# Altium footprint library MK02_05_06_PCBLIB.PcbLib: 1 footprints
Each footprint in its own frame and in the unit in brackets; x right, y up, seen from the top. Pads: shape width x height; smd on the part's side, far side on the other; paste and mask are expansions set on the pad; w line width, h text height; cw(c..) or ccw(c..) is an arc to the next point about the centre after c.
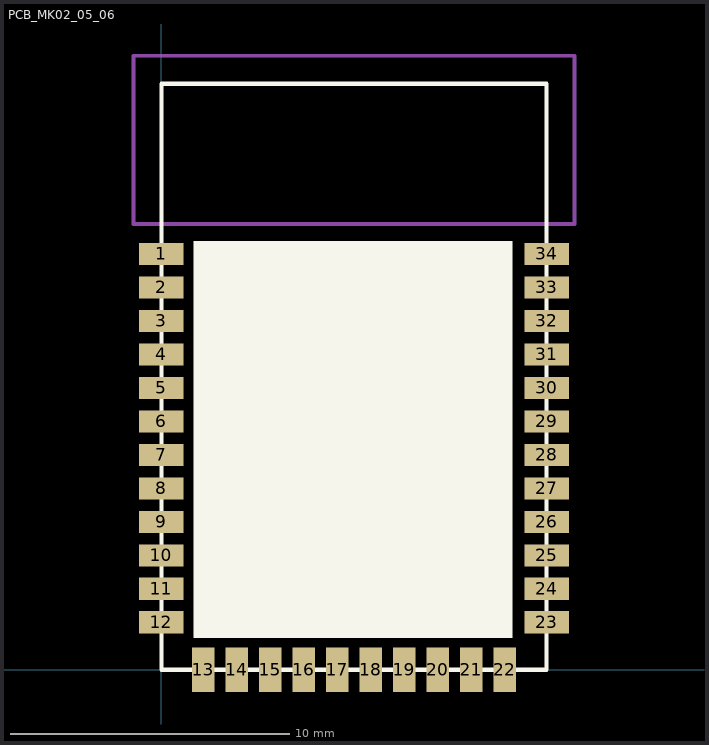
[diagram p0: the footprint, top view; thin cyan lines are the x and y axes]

## PCB_MK02_05_06 [mm] "21.0*13.8mm"
height 2
pads (34):
  rect 1.6x0.8 smd: 1(0,14.9) 2(0,13.7) 3(0,12.5) 4(0,11.3) 5(0,10.1) 6(0,8.9) 7(0,7.7) 8(0,6.5) 9(0,5.3) 10(0,4.1) 11(0,2.9) 12(0,1.7) 23(13.8,1.7) 24(13.8,2.9) 25(13.8,4.1) 26(13.8,5.3) 27(13.8,6.5) 28(13.8,7.7) 29(13.8,8.9) 30(13.8,10.1) 31(13.8,11.3) 32(13.8,12.5) 33(13.8,13.7) 34(13.8,14.9)
  rect 0.8x1.6 smd: 13(1.5,0) 14(2.7,0) 15(3.9,0) 16(5.1,0) 17(6.3,0) 18(7.5,0) 19(8.7,0) 20(9.9,0) 21(11.1,0) 22(12.3,0)
Top Overlay:
  rectangle: 1.143,1.143 12.573,15.367
  lines w0.152: 0,0 0,21 13.8,21 13.8,0 0,0
Mechanical 2:
  lines w0.127: -1,15.975 14.8,15.975 14.8,22 -1,22 -1,15.975
  text "No ground pad" at 2.311,18.136 h0.8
